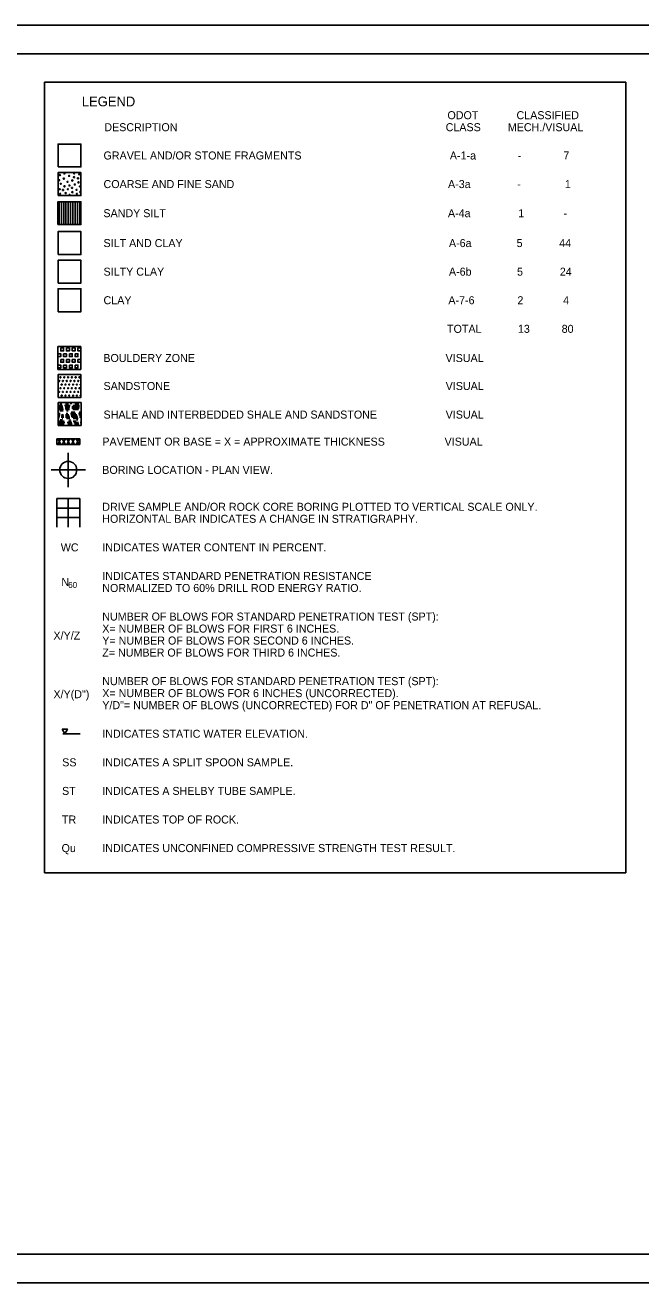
# Model space of a CAD drawing. Extents: x 0 to 34, y 0 to 22.
# Drawn here: x 11.83 to 22.6, y 0 to 22 of the extents above; entities that cross this region are included whole.
import ezdxf

# ---------------------------------------------------------------- set-up
doc = ezdxf.new("R2010")
doc.units = 0
for name, color, linetype in [('Default', 7, 'Continuous'), ('GT_Project_Soil_Boring', 7, 'Continuous'), ('GT_Project_Soil_Layers', 7, 'Continuous'), ('SH_Border', 7, 'Continuous'), ('SH_Cut_Line', 7, 'Continuous'), ('SH_Data', 7, 'Continuous'), ('SH_Text', 7, 'Continuous')]:
    doc.layers.add(name, color=color, linetype=linetype)

msp = doc.modelspace()

# ---------------------------------------------------------------- linework, layer by layer
at = {"layer": 'Default'}
for p, q in [((12.403, 19.42), (12.403, 19.42)), ((12.803, 19.42), (12.803, 19.42)), ((12.403, 19.02), (12.403, 19.02)), ((12.803, 19.02), (12.803, 19.02)), ((12.401, 18.911), (12.401, 18.911)), ((12.421, 18.511), (12.421, 18.911)), ((12.461, 18.511), (12.461, 18.911)), ((12.501, 18.511), (12.501, 18.911)), ((12.541, 18.511), (12.541, 18.911)), ((12.581, 18.511), (12.581, 18.911)), ((12.621, 18.511), (12.621, 18.911)), ((12.661, 18.511), (12.661, 18.911)), ((12.701, 18.511), (12.701, 18.911)), ((12.741, 18.511), (12.741, 18.911)), ((12.781, 18.511), (12.781, 18.911)), ((12.801, 18.911), (12.801, 18.911)), ((12.401, 18.511), (12.401, 18.511)), ((12.801, 18.511), (12.801, 18.511)), ((12.4, 16.378), (12.4, 16.378)), ((12.8, 16.378), (12.8, 16.378)), ((12.4, 15.978), (12.4, 15.978)), ((12.403, 15.884), (12.403, 15.884)), ((12.8, 15.978), (12.8, 15.978)), ((12.803, 15.884), (12.803, 15.884)), ((12.403, 15.72), (12.403, 15.703)), ((12.803, 15.703), (12.803, 15.72)), ((12.403, 15.53), (12.403, 15.513)), ((12.403, 15.503), (12.403, 15.503)), ((12.803, 15.53), (12.803, 15.513)), ((12.803, 15.503), (12.803, 15.503)), ((12.405, 15.387), (12.405, 15.387)), ((12.416, 15.231), (12.405, 15.231)), ((12.437, 15.208), (12.405, 15.208)), ((12.437, 15.186), (12.405, 15.186)), ((12.494, 15.299), (12.41, 15.299)), ((12.498, 15.277), (12.41, 15.277)), ((12.488, 15.322), (12.412, 15.322)), ((12.481, 15.345), (12.415, 15.345)), ((12.466, 15.368), (12.431, 15.368)), ((12.491, 15.254), (12.435, 15.254)), ((12.499, 15.186), (12.463, 15.186)), ((12.482, 15.208), (12.478, 15.208)), ((12.612, 15.345), (12.518, 15.345)), ((12.609, 15.322), (12.524, 15.322)), ((12.605, 15.299), (12.529, 15.299)), ((12.604, 15.277), (12.531, 15.277)), ((12.587, 15.368), (12.534, 15.368)), ((12.59, 15.186), (12.534, 15.186)), ((12.576, 15.208), (12.542, 15.208)), ((12.577, 15.254), (12.551, 15.254)), ((12.643, 15.384), (12.616, 15.384)), ((12.716, 15.208), (12.622, 15.208)), ((12.731, 15.186), (12.626, 15.186)), ((12.697, 15.231), (12.629, 15.231)), ((12.777, 15.322), (12.644, 15.322)), ((12.772, 15.299), (12.645, 15.299)), ((12.777, 15.345), (12.658, 15.345)), ((12.759, 15.277), (12.658, 15.277)), ((12.766, 15.368), (12.695, 15.368)), ((12.805, 15.208), (12.761, 15.208)), ((12.805, 15.186), (12.767, 15.186)), ((12.805, 15.231), (12.772, 15.231)), ((12.805, 15.387), (12.805, 15.387)), ((12.432, 15.163), (12.405, 15.163)), ((12.427, 15.14), (12.405, 15.14)), ((12.419, 15.117), (12.405, 15.117)), ((12.509, 15.072), (12.405, 15.072)), ((12.52, 15.049), (12.405, 15.049)), ((12.405, 15.006), (12.405, 15.006)), ((12.507, 15.026), (12.416, 15.026)), ((12.482, 15.095), (12.438, 15.095)), ((12.504, 15.163), (12.458, 15.163)), ((12.502, 15.14), (12.458, 15.14)), ((12.488, 15.117), (12.475, 15.117)), ((12.601, 15.163), (12.535, 15.163)), ((12.608, 15.14), (12.535, 15.14)), ((12.607, 15.117), (12.548, 15.117)), ((12.644, 15.049), (12.564, 15.049)), ((12.65, 15.026), (12.576, 15.026)), ((12.632, 15.072), (12.584, 15.072)), ((12.619, 15.095), (12.602, 15.095)), ((12.742, 15.163), (12.634, 15.163)), ((12.749, 15.14), (12.646, 15.14)), ((12.753, 15.117), (12.668, 15.117)), ((12.717, 15.072), (12.668, 15.072)), ((12.76, 15.049), (12.679, 15.049)), ((12.763, 15.026), (12.691, 15.026)), ((12.75, 15.095), (12.726, 15.095)), ((12.805, 15.163), (12.776, 15.163)), ((12.805, 15.14), (12.776, 15.14)), ((12.792, 15.049), (12.805, 15.049)), ((12.805, 15.117), (12.794, 15.117)), ((12.795, 15.072), (12.805, 15.072)), ((12.805, 15.006), (12.805, 15.006)), ((12.488, 9.605), (12.788, 9.605))]:
    msp.add_line(p, q, dxfattribs=at)
for points in [[(12.45, 16.353), (12.5, 16.353), (12.5, 16.303), (12.45, 16.303)], [(12.55, 16.353), (12.6, 16.353), (12.6, 16.303), (12.55, 16.303)], [(12.65, 16.353), (12.7, 16.353), (12.7, 16.303), (12.65, 16.303)], [(12.75, 16.353), (12.8, 16.353), (12.8, 16.303), (12.75, 16.303)], [(12.4, 16.253), (12.45, 16.253), (12.45, 16.203), (12.4, 16.203)], [(12.45, 16.153), (12.5, 16.153), (12.5, 16.103), (12.45, 16.103)], [(12.5, 16.253), (12.55, 16.253), (12.55, 16.203), (12.5, 16.203)], [(12.55, 16.153), (12.6, 16.153), (12.6, 16.103), (12.55, 16.103)], [(12.6, 16.253), (12.65, 16.253), (12.65, 16.203), (12.6, 16.203)], [(12.65, 16.153), (12.7, 16.153), (12.7, 16.103), (12.65, 16.103)], [(12.7, 16.253), (12.75, 16.253), (12.75, 16.203), (12.7, 16.203)], [(12.75, 16.153), (12.8, 16.153), (12.8, 16.103), (12.75, 16.103)], [(12.4, 16.053), (12.45, 16.053), (12.45, 16.003), (12.4, 16.003)], [(12.5, 16.053), (12.55, 16.053), (12.55, 16.003), (12.5, 16.003)], [(12.6, 16.053), (12.65, 16.053), (12.65, 16.003), (12.6, 16.003)], [(12.7, 16.053), (12.75, 16.053), (12.75, 16.003), (12.7, 16.003)], [(12.472, 9.687), (12.566, 9.687), (12.519, 9.605)]]:
    msp.add_lwpolyline(points, close=True, dxfattribs=at)
for centre, radius in [((12.433, 19.379), 0.00954), ((12.514, 19.404), 0.00954), ((12.597, 19.363), 0.00954), ((12.684, 19.407), 0.00954), ((12.775, 19.394), 0.00954), ((12.421, 19.288), 0.00954), ((12.45, 19.226), 0.00954), ((12.503, 19.314), 0.00954), ((12.515, 19.18), 0.00954), ((12.569, 19.259), 0.00954), ((12.601, 19.195), 0.00954), ((12.646, 19.153), 0.00954), ((12.653, 19.283), 0.00954), ((12.681, 19.341), 0.00954), ((12.696, 19.213), 0.00954), ((12.752, 19.32), 0.00954), ((12.76, 19.251), 0.00954), ((12.785, 19.179), 0.00954), ((12.432, 19.13), 0.00954), ((12.441, 19.049), 0.00954), ((12.489, 19.117), 0.00954), ((12.536, 19.063), 0.00954), ((12.575, 19.13), 0.00954), ((12.604, 19.03), 0.00954), ((12.652, 19.078), 0.00954), ((12.726, 19.12), 0.00954), ((12.732, 19.05), 0.00954), ((12.792, 19.081), 0.00954), ((12.444, 15.839), 0.0091), ((12.51, 15.839), 0.0091), ((12.577, 15.839), 0.0091), ((12.644, 15.839), 0.0091), ((12.71, 15.839), 0.0091), ((12.777, 15.839), 0.0091), ((12.422, 15.775), 0.0091), ((12.444, 15.648), 0.0091), ((12.466, 15.712), 0.0091), ((12.488, 15.775), 0.0091), ((12.51, 15.648), 0.0091), ((12.533, 15.712), 0.0091), ((12.555, 15.775), 0.0091), ((12.577, 15.648), 0.0091), ((12.599, 15.712), 0.0091), ((12.622, 15.775), 0.0091), ((12.644, 15.648), 0.0091), ((12.666, 15.712), 0.0091), ((12.688, 15.775), 0.0091), ((12.71, 15.648), 0.0091), ((12.732, 15.712), 0.0091), ((12.755, 15.775), 0.0091), ((12.777, 15.648), 0.0091), ((12.421, 15.585), 0.0091), ((12.466, 15.521), 0.0091), ((12.488, 15.585), 0.0091), ((12.533, 15.521), 0.0091), ((12.555, 15.585), 0.0091), ((12.599, 15.521), 0.0091), ((12.621, 15.585), 0.0091), ((12.666, 15.521), 0.0091), ((12.688, 15.585), 0.0091), ((12.732, 15.521), 0.0091), ((12.755, 15.585), 0.0091)]:
    msp.add_circle(centre, radius, dxfattribs=at)
for centre, radius, start, end in [((12.399, 15.712), 0.0091, 290.8521, 69.1479), ((12.799, 15.712), 0.00918, 67.9141, 292.0859), ((12.399, 15.521), 0.0091, 291.3407, 68.6593), ((12.799, 15.521), 0.00918, 67.4298, 292.5702)]:
    msp.add_arc(centre, radius, start, end, dxfattribs=at)
at = {"layer": 'GT_Project_Soil_Boring'}
for p, q in [((12.581, 14.22), (12.581, 14.52)), ((12.581, 14.37), (12.581, 14.22)), ((12.581, 14.22), (12.281, 14.22)), ((12.581, 14.22), (12.431, 14.22)), ((12.581, 14.22), (12.581, 13.92)), ((12.581, 14.22), (12.881, 14.22)), ((12.581, 14.07), (12.581, 14.22)), ((12.581, 14.22), (12.731, 14.22)), ((12.381, 13.72), (12.781, 13.72)), ((12.381, 13.72), (12.381, 13.22)), ((12.581, 13.72), (12.581, 13.22)), ((12.781, 13.72), (12.781, 13.22)), ((12.381, 13.553), (12.781, 13.553)), ((12.381, 13.387), (12.781, 13.387))]:
    msp.add_line(p, q, dxfattribs=at)
msp.add_circle((12.581, 14.22), 0.15, dxfattribs=at)
for start, end in [(90, 180), (270, 360)]:
    msp.add_arc((12.581, 14.22), 0.15, start, end, dxfattribs=at)
at = {"layer": 'GT_Project_Soil_Layers'}
for p, q in [((12.397, 14.765), (12.45, 14.665)), ((12.397, 14.665), (12.45, 14.765)), ((12.477, 14.765), (12.53, 14.665)), ((12.477, 14.665), (12.53, 14.765)), ((12.557, 14.765), (12.61, 14.665)), ((12.557, 14.665), (12.61, 14.765)), ((12.637, 14.765), (12.69, 14.665)), ((12.637, 14.665), (12.69, 14.765)), ((12.717, 14.765), (12.77, 14.665)), ((12.717, 14.665), (12.77, 14.765))]:
    msp.add_line(p, q, dxfattribs=at)
at = {"layer": 'SH_Border'}
msp.add_lwpolyline([(2, 21.5), (33.5, 21.5), (33.5, 0.5), (2, 0.5)], close=True, dxfattribs=at)
at = {"layer": 'SH_Cut_Line'}
msp.add_lwpolyline([(0, 0), (34, 0), (34, 22), (0, 22)], close=True, dxfattribs=at)
at = {"layer": 'SH_Data'}
for p, q in [((12.167, 7.175), (12.167, 21)), ((22.333, 21), (12.167, 21)), ((22.333, 7.175), (22.333, 21)), ((12.383, 14.665), (12.383, 14.765)), ((12.383, 14.765), (12.783, 14.765)), ((12.783, 14.665), (12.783, 14.765)), ((12.383, 14.665), (12.783, 14.665)), ((22.333, 7.175), (12.167, 7.175))]:
    msp.add_line(p, q, dxfattribs=at)
for points in [[(12.403, 19.52), (12.803, 19.52), (12.803, 19.92), (12.403, 19.92)], [(12.403, 19.02), (12.803, 19.02), (12.803, 19.42), (12.403, 19.42)], [(12.401, 18.511), (12.801, 18.511), (12.801, 18.911), (12.401, 18.911)], [(12.403, 17.988), (12.803, 17.988), (12.803, 18.388), (12.403, 18.388)], [(12.403, 17.488), (12.803, 17.488), (12.803, 17.888), (12.403, 17.888)], [(12.403, 16.988), (12.803, 16.988), (12.803, 17.388), (12.403, 17.388)], [(12.4, 15.978), (12.8, 15.978), (12.8, 16.378), (12.4, 16.378)], [(12.403, 15.488), (12.803, 15.488), (12.803, 15.888), (12.403, 15.888)], [(12.405, 14.999), (12.805, 14.999), (12.805, 15.399), (12.405, 15.399)]]:
    msp.add_lwpolyline(points, close=True, dxfattribs=at)

# ---------------------------------------------------------------- texts
at = {"layer": 'SH_Text'}
for s, height, p in [('LEGEND', 0.17, (12.818, 20.58)), ('ODOT', 0.14, (19.215, 20.355)), ('CLASSIFIED', 0.14, (20.423, 20.355)), ('DESCRIPTION', 0.14, (13.212, 20.145)), ('CLASS', 0.14, (19.184, 20.145)), ('MECH./VISUAL', 0.14, (20.271, 20.145)), ('GRAVEL AND/OR STONE FRAGMENTS                ', 0.14, (13.198, 19.65)), (' A-1-a', 0.14, (19.205, 19.65)), (' - ', 0.14, (20.392, 19.65)), (' 7 ', 0.14, (21.191, 19.65)), ('COARSE AND FINE SAND                         ', 0.14, (13.198, 19.15)), (' A-3a ', 0.14, (19.173, 19.15)), (' - ', 0.14, (20.383, 19.15)), (' 1 ', 0.14, (21.217, 19.15)), ('SANDY SILT                                   ', 0.14, (13.196, 18.641)), (' A-4a ', 0.14, (19.172, 18.641)), (' 1 ', 0.14, (20.403, 18.641)), (' - ', 0.14, (21.194, 18.641)), ('SILT AND CLAY                                ', 0.14, (13.198, 18.118)), (' A-6a ', 0.14, (19.189, 18.118)), (' 5 ', 0.14, (20.373, 18.118)), (' 44 ', 0.14, (21.118, 18.118)), ('SILTY CLAY                                   ', 0.14, (13.198, 17.618)), (' A-6b ', 0.14, (19.189, 17.618)), (' 5 ', 0.14, (20.38, 17.618)), (' 24 ', 0.14, (21.129, 17.618)), ('CLAY                                         ', 0.14, (13.198, 17.118)), (' A-7-6', 0.14, (19.179, 17.118)), (' 2 ', 0.14, (20.387, 17.118)), ('4 ', 0.14, (21.239, 17.118)), (' TOTAL', 0.14, (19.156, 16.618)), ('13', 0.14, (20.448, 16.618)), ('80', 0.14, (21.213, 16.618)), ('BOULDERY ZONE                                ', 0.14, (13.195, 16.108)), ('VISUAL', 0.14, (19.182, 16.108)), ('SANDSTONE                                    ', 0.14, (13.198, 15.618)), ('VISUAL', 0.14, (19.184, 15.618)), ('SHALE AND INTERBEDDED SHALE AND SANDSTONE    ', 0.14, (13.198, 15.118)), ('VISUAL', 0.14, (19.184, 15.118)), ('PAVEMENT OR BASE = X = APPROXIMATE THICKNESS', 0.14, (13.178, 14.645)), ('VISUAL', 0.14, (19.165, 14.645)), ('BORING LOCATION - PLAN VIEW.', 0.14, (13.176, 14.15)), ('DRIVE SAMPLE AND/OR ROCK CORE BORING PLOTTED TO VERTICAL SCALE ONLY.', 0.14, (13.176, 13.505)), ('HORIZONTAL BAR INDICATES A CHANGE IN STRATIGRAPHY.', 0.14, (13.176, 13.295)), ('WC', 0.14, (12.45, 12.795)), ('INDICATES WATER CONTENT IN PERCENT.', 0.14, (13.176, 12.795)), ('N', 0.14, (12.46, 12.19)), ('INDICATES STANDARD PENETRATION RESISTANCE', 0.14, (13.176, 12.295)), ('60', 0.105, (12.58, 12.155)), ('NORMALIZED TO 60% DRILL ROD ENERGY RATIO.', 0.14, (13.176, 12.085)), ('NUMBER OF BLOWS FOR STANDARD PENETRATION TEST (SPT):', 0.14, (13.176, 11.585)), ('X= NUMBER OF BLOWS FOR FIRST 6 INCHES.', 0.14, (13.176, 11.375)), ('X/Y/Z', 0.14, (12.322, 11.252)), ('Y= NUMBER OF BLOWS FOR SECOND 6 INCHES.', 0.14, (13.176, 11.165)), ('Z= NUMBER OF BLOWS FOR THIRD 6 INCHES.', 0.14, (13.176, 10.955)), ('NUMBER OF BLOWS FOR STANDARD PENETRATION TEST (SPT):', 0.14, (13.176, 10.455)), ('X/Y(D")', 0.14, (12.322, 10.227)), ('X= NUMBER OF BLOWS FOR 6 INCHES (UNCORRECTED).', 0.14, (13.176, 10.245)), ('Y/D"= NUMBER OF BLOWS (UNCORRECTED) FOR D" OF PENETRATION AT REFUSAL.', 0.14, (13.176, 10.035)), ('INDICATES STATIC WATER ELEVATION.', 0.14, (13.176, 9.535)), ('SS', 0.14, (12.475, 9.035)), ('INDICATES A SPLIT SPOON SAMPLE.', 0.14, (13.176, 9.035)), ('ST', 0.14, (12.472, 8.535)), ('INDICATES A SHELBY TUBE SAMPLE.', 0.14, (13.176, 8.535)), ('TR', 0.14, (12.47, 8.035)), ('INDICATES TOP OF ROCK.', 0.14, (13.176, 8.035)), ('Qu', 0.14, (12.464, 7.535)), ('INDICATES UNCONFINED COMPRESSIVE STRENGTH TEST RESULT.', 0.14, (13.176, 7.535))]:
    msp.add_text(s, height=height, dxfattribs=at).set_placement(p)

doc.saveas('drawing.dxf')
